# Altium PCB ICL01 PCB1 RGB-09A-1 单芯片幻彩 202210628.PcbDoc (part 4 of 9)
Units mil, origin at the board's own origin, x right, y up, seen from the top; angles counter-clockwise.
Board outline 17436.43 x 6581.89 mil, 2 copper layers (Top Layer, Bottom Layer), stack 65.792 mil thick; 425 components, 516 nets, 1625 pads, 2772 vias.
Unrouted connection lines stored in the file: 1.
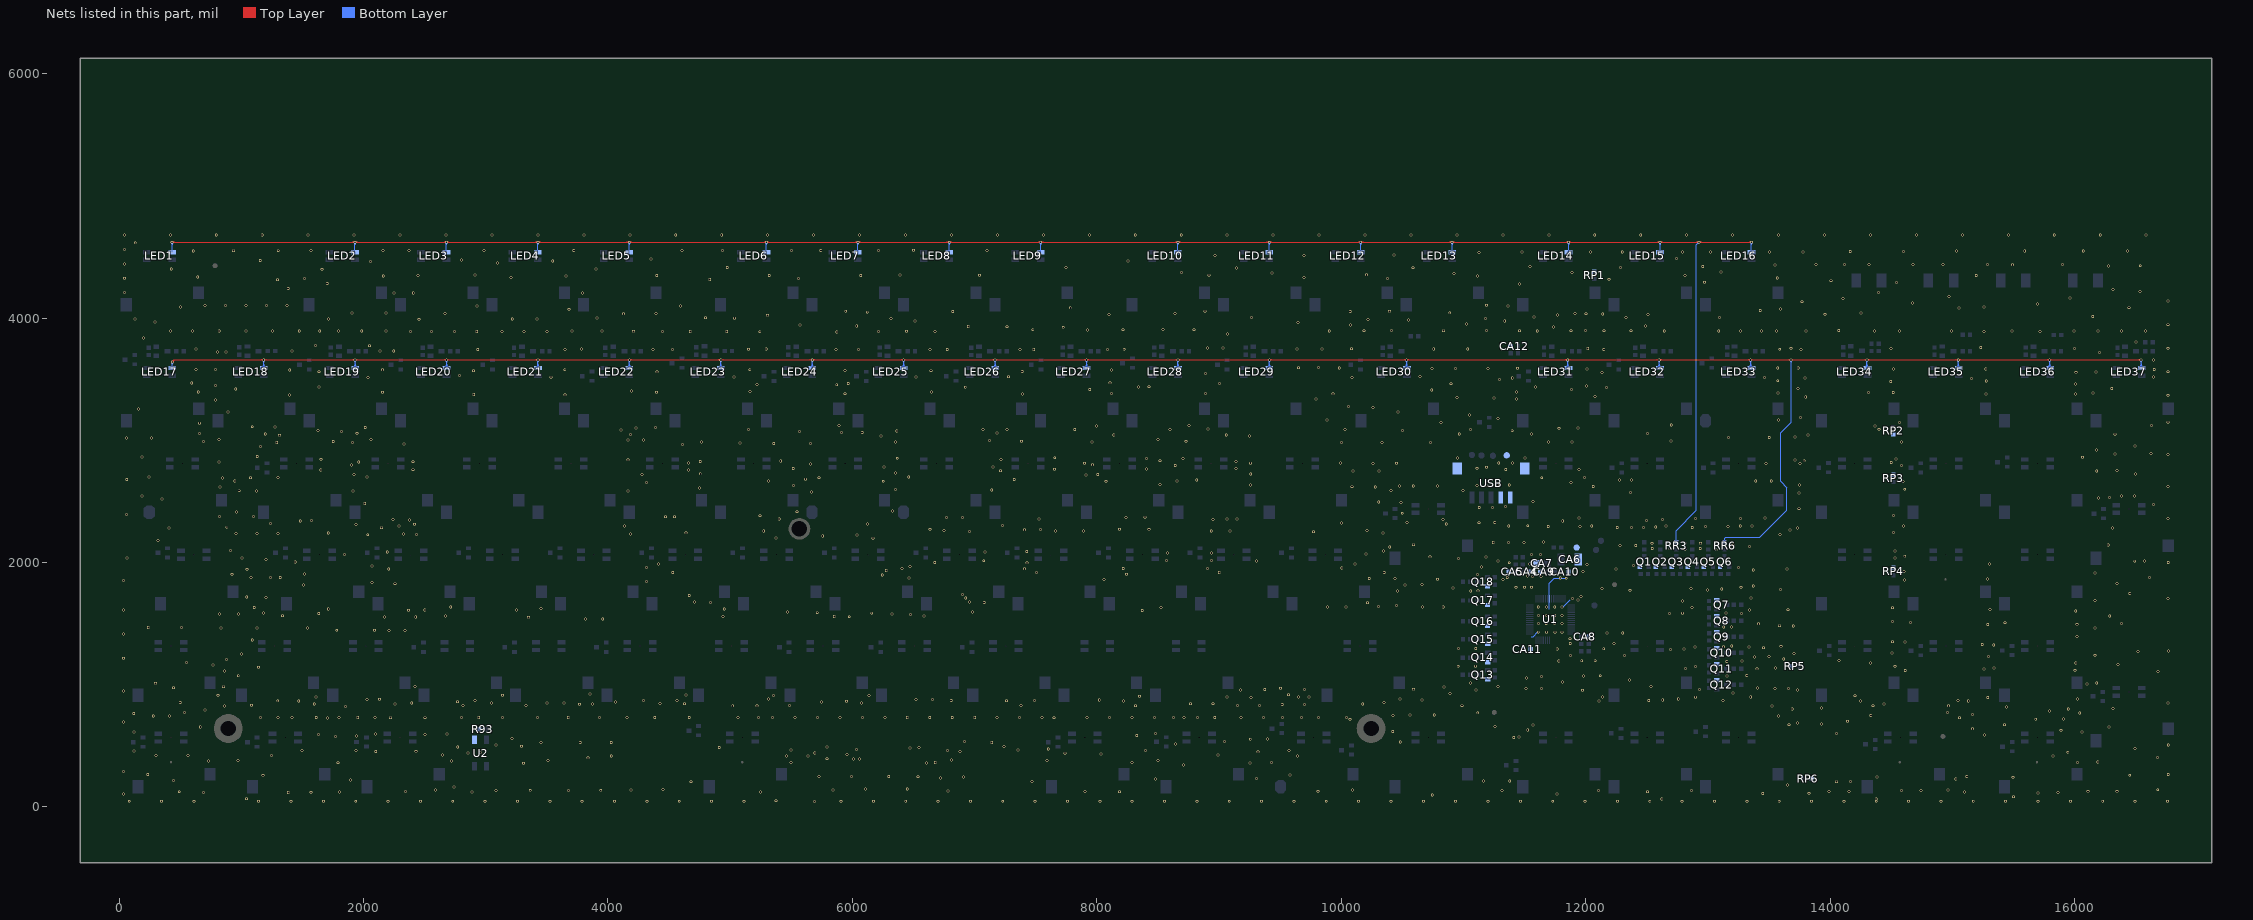
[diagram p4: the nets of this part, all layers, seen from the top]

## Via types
v1: diameter 23.62, hole 15.75, Top Layer to Bottom Layer, tented both sides, 2766 vias
v2: diameter 19.68, hole 11.81, Top Layer to Bottom Layer, tented both sides, 6 vias

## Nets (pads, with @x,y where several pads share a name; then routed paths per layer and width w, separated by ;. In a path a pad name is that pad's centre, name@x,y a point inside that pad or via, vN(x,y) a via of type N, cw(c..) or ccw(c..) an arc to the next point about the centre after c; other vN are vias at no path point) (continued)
GND: CA4.2 CA5.2 CA6.2 CA7.2 CA8.1 CA9.2 CA10.1 CA11.1 CA12.1 pad.3 pad.12 Q1.E Q2.E Q3.E Q4.E Q5.E Q6.E Q7.E Q8.E Q9.E Q10.E Q11.E Q12.E Q13.E Q14.E Q15.E Q16.E Q17.E Q18.E R93.1 RP1.1 RP2.1 RP3.1 RP4.1 RP5.1 RP6.1 U1.56 U2.3 USB.0 USB.1 USB.2 | length 519.8
  Bottom Layer w8: 11555.11,1392.82 11570.25,1392.82 v1@11609.43,1432 ; 11703.42,1617.72 U1.56@11703.42,1703.16 11703.42,1831.8 11744.32,1872.7 11838.9,1872.7 v1(11840.87,1870.73) ; v1@11817.24,1639.8 11873.8,1696.37
  other v1: 5690.72,44.71 83.93,46.43 348.61,46.43 613.3,46.43 1142.68,46.43 1407.36,46.43 1672.05,46.43 1936.74,46.43 2201.42,46.43 2466.11,46.43 2730.8,46.43 2995.49,46.43 3260.17,46.43 3524.86,46.43 3789.55,46.43 4054.23,46.43 4318.92,46.43 4583.61,46.43 4848.3,46.43 5112.98,46.43 5907.04,46.43 6171.73,46.43 6436.42,46.43 6701.11,46.43 6965.79,46.43 7230.48,46.43 7495.17,46.43 7759.85,46.43 8024.54,46.43 8289.23,46.43 8553.91,46.43 8818.6,46.43 9083.29,46.43 9347.98,46.43 9612.66,46.43 9877.35,46.43 10142.04,46.43 10406.72,46.43 10671.41,46.43 10936.1,46.43 11200.79,46.43 11465.47,46.43 11730.16,46.43 11994.85,46.43 12259.53,46.43 12524.22,46.43 12788.91,46.43 13053.6,46.43 13318.28,46.43 13582.97,46.43 13847.66,46.43 14112.34,46.43 14377.03,46.43 14641.72,46.43 14906.41,46.43 15171.09,46.43 15435.78,46.43 15700.47,46.43 15965.15,46.43 16229.84,46.43 16494.53,46.43 16759.22,46.43 5375.47,50.46 14376.62,64.25 12622.41,65.24 1043.39,66.86 15499.68,83.08 10744.58,99.22 11765.88,106.64 35.28,106.96 13448.4,108.4 13826.05,111.82 15701.46,113.59 692.61,118.76 1385.12,119.47 15863.14,118.88 1571.49,120.02 1802.83,121.46 5247.59,121.19 2889.04,122.61 15097.77,122.95 493.1,123.98 8186.31,123.98 12504.37,124.37 2345.16,126.39 7904.29,126 13991.81,126.39 14154.21,126.39 9809.38,128.17 16108.8,127.98 16347.64,127.98 6782.82,131.44 3085.11,134.09 3677.51,134.09 11314.75,134.1 12104.85,134.1 12864.84,134.26 14582.5,133.94 14741.69,135.19 3364.62,136.17 3941.38,136.17 2588.58,137.71 14963.55,137.62 4190.33,139.09 5841.63,139.14 10092.41,139.36 16680,140.49 4450.78,143.16 6448.87,146.1 6108.08,147.93 2741.98,164.33 13649.43,179.9 4681.11,205.83 14053.3,206.49 14165.9,207.19 7468.7,208.51 11378.21,210.92 11162.59,213.61 446.53,215.95 1895.37,219.72 8480.98,227.76 15027.83,228.57 9307.11,231.98 6720.41,236.25 15496.77,242.66 6910,244.49 14383.71,244.11 6535.53,246.84 5992.67,248.02 6297.66,248.02 5726.08,249.28 15117.8,249.73 1177.3,258.91 16450.8,258.94 9582.02,260.3 16766.05,265.27 234.92,266.15 35.48,290.73 8709.33,342.92 3308.74,357.69 9252.21,359.68 6605.98,360.64 1792.41,361.3 5498.7,362.61 6678.61,362.61 8287.04,363.3 9430.27,362.89 16023.49,364.54 16189.64,367.53 2720.16,374.42 731.14,375.53 972.36,378.62 3509.53,379.34 7591.04,378.86 8501.65,379.34 6809.72,385.24 6008.54,392.13 6058.56,393.17 5791.83,394.33 3837.28,401.98 16677.85,402.96 9643.43,415.51 15824.1,415.85 4027.24,417.72 5637.35,417.65 5461.21,417.84 303.82,420.68 565.63,420.68 1246.97,421.29 8990.83,423.63 2647.81,425.87 5955.94,428.88 8034.25,432.3 7741.29,439.61 5692.6,441.35 2855,442.33 2958.64,445.24 15944.24,447.59 9317.98,451.12 6879.74,454.29 2100.37,454.95 2430.66,455.21 122.14,456.18 9572.73,461.35 1497.62,462.54 1939.52,462.25 8398.3,462.65 6779.21,463 5498.7,464.97 7355,464.97 6035.12,468.9 7602.63,473.93 16492.78,478.98 6472.12,483.67 6544.96,485.64 4911.13,487.34 5793.13,489.23 2771.34,491.54 7241.81,493.51 3292.01,496.46 3083.35,505.32 16766.05,506.23 8642.84,514.99 4027.24,525.99 3451.46,526.98 3773.31,526.98 7140,527.07 10482.89,531.47 6916.75,534.47 9046.1,535.99 9255.81,553.72 9396.09,556.16 3215.67,558.5 11410.91,568.79 11455.56,571.74 1770.37,575.95 1942.38,581.91 8327.05,584.38 15261.49,587.02 1632.66,593.88 2505.05,594.18 2100.07,595.84 2682.2,597.44 8481.66,599.52 14051.85,599.81 16060.55,613.38 123.94,614.48 10420.94,615.83 15887.44,627.67 11525.33,630.27 15164.48,639.29 16282.18,653.82 665.04,654.93 11256.31,659.31 11567.19,669.92 13664.05,672.65 15426.05,672.13 13927.83,679.53 13732.68,686.3 35.28,693.82 14142.44,700.8 10070.01,717.16 15681.67,717.64 15909.71,719.93 1707.02,729.18 15058.09,729.53 1158.54,730.22 1299.96,730.22 1415.53,730.22 1613.52,730.22 1952.94,730.22 2094.36,730.22 2222.29,730 2503.44,730 2801.46,730.22 2942.89,730.22 3138.44,730.22 3423.72,730.22 3675.84,730.22 3930.4,730.22 4156.67,730.22 4382.95,730.22 4665.79,730.22 5064.21,730.22 5231.48,730.22 5346.62,730.37 5530.43,730.37 5714.24,730.37 5898.04,730.37 6081.85,730.37 6265.65,730.37 6449.46,730.37 6633.27,730.37 6817.07,730.37 7000.88,730.37 7184.69,730.37 7368.49,730.37 7552.3,730.37 7648.24,729.93 7919.91,730.37 8103.72,730.37 8287.52,730.37 8471.33,730.37 8628.03,730.22 8712.88,730.22 8823.58,730.22 8965,730.22 9363.42,730.22 9814.96,730.57 1798.77,731.34 10042.37,731.29 9179.15,731.95 9520.14,733.18 9674.6,732.78 280.38,744.06 411.74,744.69 13576.57,744.14 10423.74,746.7 14332.36,749.42 10562.32,752.59 10760.62,751.86 15165.76,754.74 120.7,764.75 16041.78,767.41 11116.64,770.21 535.5,773.45 14958.55,772.93 15794.96,783.87 704.71,794.01 13689.44,800.87 15947.98,801.05 16314.94,805.9 13928.86,808.79 15441.78,818.36 1851.99,821.79 862.14,824.44 5021.07,827.5 5219.06,827.5 8315.8,827.71 13523.4,826.97 14968.36,827.49 2814.38,828.73 3330.57,828.66 10988.68,828.24 14351.06,828.16 5485.45,829.1 7380.33,829.59 9149.5,830.79 9331.36,831.38 1083.72,832.25 9698.11,837.39 9516.77,839.32 3768.38,839.97 1597.26,841.73 2257.2,840.87 10175.57,841.36 14439.07,842.01 3875.47,843.02 4626.44,844.44 8766.05,844.33 8950.37,844.16 4427.1,844.79 3046.93,848.83 3639.63,849.43 2394.89,850.14 6073.72,850.54 16764.5,850.98 3502.64,851.78 500.65,855.6 10350.56,856.03 4063.09,857.87 2768.38,860.64 5748.9,859.85 5950.71,864.54 8218.78,865.33 14246.73,865.56 12110.25,865.96 1470.49,867.46 15130.07,867.6 1298.48,868.45 7262.51,868.57 4290.04,869.5 7490.17,869.32 4564.64,870.48 15046.76,870.14 2911.08,871.02 6808.74,871.46 12515.56,871.76 13122.96,871.62 8020.35,873.43 12629.95,873.34 10660.01,875 6521.34,878.35 6657.16,878.35 2029.21,879.34 2132.18,881.19 10479.5,881.75 5314.04,882.74 16023.4,882.92 12757.51,884.41 9261.57,895.39 15289.4,896.85 1610.43,897.88 12136.51,898.16 12897.45,897.87 13349.84,898.26 9650.35,898.86 9736.33,899.59 9063.99,900.64 8350.11,905.76 14202.71,909.44 6135.15,912.43 810.2,913.53 5355.11,913.19 3136.08,914.02 4638.74,914.43 9569.29,917.78 3851.99,922.91 10889.74,927.18 13204.07,933.4 35.28,948.38 9176.91,955.52 11102.62,955.56 11973.28,954.84 13732.27,955.49 9373.73,959.58 9697.91,960.42 10592.28,962.55 12929.54,961.96 11511.31,969.04 13547.5,969.43 13659.48,969.43 11639.05,970.46 9502.41,970.83 13405.04,971.55 446.01,974.99 10840.97,981.26 855.98,983.67 12533.15,984.65 2420.15,986.68 11282.42,986.68 16100.76,1004.94 299.41,1011.59 11058.15,1014.61 16181.27,1014.4 11808.65,1022.26 12357.01,1038.18 11514.86,1056.32 11636.92,1068.39 11981.09,1072.64 13154.85,1072.2 975.96,1073.23 12118.97,1073.39 13317.86,1075.03 16682.65,1107.01 862.25,1113.29 14614.14,1116.04 16001.65,1118.51 15259.89,1128.67 13401.58,1130.27 12815.74,1133.28 13551.41,1136.36 15341.71,1136.51 1141.84,1142.86 12899.29,1149.02 10956.71,1150.79 11099.84,1151.49 14531.18,1150.99 769.67,1161.12 16354.05,1166.5 14328.42,1177.57 16009.63,1179.04 551.71,1182.4 13154.21,1188.39 11779.75,1195.52 13278.76,1194.88 11967.22,1195.83 12077.6,1196.12 14071.39,1196.51 879.38,1207.37 13620.21,1208.79 35.28,1216.73 13379.74,1226.62 13500.57,1229.26 15295.38,1231.59 11877.07,1238.98 12317.73,1239.74 16166.72,1240.73 1003.44,1251.45 13704.35,1254.13 14504.61,1258.28 16519.61,1270.17 16766.6,1276.99 12693.55,1288.5 12804.43,1292.6 11766.78,1293.48 12147.14,1294.05 10958.1,1296.7 11100.53,1296.01 13455.79,1302.33 12894.29,1306.98 13336.15,1309.01 13126.38,1310.17 13598.66,1314.23 13194.58,1316.03 15338.24,1324.44 15244.22,1329.54 12230.88,1337.34 11873.7,1338 14611.71,1350.5 14510.31,1351.56 1090.32,1366.68 11872.17,1375.87 16021.08,1395.74 35.28,1414.72 12175.27,1422.08 12302.91,1424.4 11611.89,1429.53 11678.82,1429.53 11747.72,1429.53 11806.77,1429.53 2340.6,1443.21 1781.31,1445.48 2090.32,1445.46 2209.15,1445.08 1541.98,1463.52 1129.62,1464.19 834.81,1465.49 16166.72,1465.12 239.67,1466.58 511.54,1466.72 13129.62,1473.21 13191.46,1472.8 13697.88,1481.42 13584.47,1482.71 15288.99,1491.25 16020.01,1494.31 13414.18,1498.4 11612.87,1499.42 11806.77,1499.42 11676.85,1500.4 11745.75,1500.4 16384.17,1501.26 15430.07,1506.8 14656.22,1508.09 14508.54,1516.15 3816.87,1537.78 3957.51,1538.99 3350.84,1551.61 2172.91,1552.75 2427.47,1554.83 5974.82,1555.98 4941.18,1557.93 5852.24,1558.06 6586.38,1561.58 16287.51,1561.06 2671.38,1563.64 1339.01,1563.97 11613.86,1566.35 11677.83,1566.35 11806.77,1566.35 11746.73,1567.33 6474.94,1575.27 823.4,1578.02 976.94,1578.84 6323.1,1580.08 13273.21,1581.8 1634.13,1582.96 12685.71,1584.06 6158.56,1585.05 12792.01,1585.05 1181.2,1587.22 13147.32,1588 5712.68,1589.2 6983.81,1593.73 5469.32,1594.97 16009,1602.27 8371.83,1606.24 2369.59,1609.49 2501.83,1609.77 13339.92,1611.72 35.28,1612.72 3252.43,1612 13653.95,1613.19 15308.4,1614.82 1712.31,1620.31 4951.96,1620.71 3451.46,1624.42 14509.51,1629.46 1106.23,1631.06 8526.61,1631.56 12868.06,1632.05 2714.37,1634.56 10664.35,1635.17 10834.05,1635.17 11611.89,1635.24 11677.83,1635.24 11746.73,1635.24 11806.77,1635.24 9888.1,1637.25 10037.88,1637.25 10305.25,1641.44 10452.44,1648.04 10214.37,1670.5 4838.72,1672.85 7078.61,1674.04 4709.41,1676.51 6958.8,1677.5 12792.01,1684.46 16166.72,1689.5 11936.56,1691.94 11893.38,1704.14 16764.65,1705.44 6927.47,1708.19 13353.16,1710.8 1203.9,1714.38 1045.06,1716.84 11962.87,1720.44 4665.68,1728.92 6902.24,1738.59 16451.53,1746.74 11059.4,1765.56 10458.92,1767.61 11118.25,1768.37 12362.87,1773.04 12995.75,1775.01 13592.14,1777.82 13112.87,1783.87 12860.9,1785.83 12133.24,1788.44 10913.67,1792.29 11430.49,1797.47 11498.46,1797.47 11556.54,1797.47 13269.37,1797.65 13370.75,1808.47 10522.9,1815.44 1508.44,1816.32 10661.59,1819.5 2257.18,1826.42 16345.54,1829.21 2068.65,1835.89 4314.5,1845.19 35.28,1853.48 14608.83,1856.61 11324.71,1859.6 8059.42,1862.08 10787.35,1863.01 15287.79,1864.17 10229.23,1868.6 10439.19,1870.45 11791.61,1872.7 6462.91,1874.37 1079.41,1876.39 1237.87,1876.39 11357.9,1877.39 1319.51,1878.71 16614,1878.26 11566.17,1886.46 11634.81,1886.46 11523.3,1889.3 6244.25,1898.89 925.18,1903.48 8243.97,1903.67 11114.31,1902.85 1518.93,1906.94 16166.72,1913.89 9002.09,1916.59 10351.29,1917.69 4530.66,1917.95 7507.96,1918.06 11978.08,1927.28 14605.59,1927.73 6277.62,1935.94 13370.75,1937.41 1045.83,1944.44 2207.11,1945.89 12248.36,1946.7 13646.87,1945.93 7407.45,1948.37 8905.68,1949.21 6405.73,1949.85 8216.25,1949.97 10004.36,1953.61 4314.5,1960.41 13250.22,1960.5 11146.38,1962.73 6472.36,1967.22 2068.65,1969.72 12392.26,1973.99 12009.94,1984.5 4414.95,1987.23 10112,1987.39 11539.19,1988.11 15302.22,1988.08 7429.65,1997.52 11374.39,1997.8 6674.16,2000.76 16765.77,2000.87 1441.53,2005.1 16492.13,2010.42 9307.29,2011.31 11281.65,2013.54 16572.51,2013.03 7074.73,2014.38 8571.54,2014.77 8936.81,2015.09 1201.53,2025.87 10959.63,2031.82 66.02,2037.2 1006.57,2037.8 14529.21,2037.8 11866.43,2043.14 11184.93,2045.38 10725.74,2046.5 14609.85,2050.65 11631.01,2064.43 11555.35,2065.39 1846.38,2066.17 10202.51,2068.6 8578.84,2078.06 8938.37,2077.9 2194.74,2086.06 7083.81,2086.98 7426.61,2090.42 10345.37,2093.43 14529.21,2092.92 913.14,2098.82 13068,2103.75 12812.19,2105.16 12544.13,2113.17 12684.52,2115.05 12937.03,2115.52 10396.96,2126.26 13340.27,2130.35 12280.32,2140.02 12409.12,2140.02 13208.09,2143.69 16274.79,2144.23 10590.28,2145.42 12543.19,2157.45 12681.69,2157.45 12938.44,2156.98 13068.47,2158.39 12813.13,2158.87 11243.88,2162.56 11369.82,2163.06 11495.26,2163.57 11653.57,2166.31 318.34,2178.48 6168.06,2198.59 5376.3,2201.29 5757.33,2216.38 2034.85,2226.72 6037.53,2225.82 2434.42,2227.76 13588.49,2229.4 4186.3,2231.87 2326.33,2233.82 1300.28,2235.58 1129.61,2237.61 957.36,2238.59 1711.78,2240.69 10339.92,2242.1 4639.56,2242.82 14518.78,2244.31 9771.4,2251.29 6957.33,2254.19 5274.67,2257.19 7663.2,2257.27 7891.31,2257.68 9088.19,2257.68 8936.55,2257.77 6749.61,2260.98 10209.04,2263.07 7408.18,2267.47 13671.86,2266.8 7539.96,2268.41 8428.27,2271.55 6634.04,2271.77 8186.79,2272.11 408.56,2280.7 13733.79,2283.1 16309.73,2283.15 2149.16,2284.56 12474.07,2285.62 12257.98,2285.95 12374.4,2286.74 12871.33,2286.52 881.93,2288.61 12573.09,2289.95 12979.21,2293.28 11693.37,2294.5 11954.26,2295 13165.62,2295.16 11370.55,2297.13 12049.42,2297.52 14600.69,2297.28 4136.22,2298.16 13264.64,2298 12655.54,2299.59 13361.27,2299.37 2292.05,2299.79 11525.66,2300.77 7226.9,2302.46 1938.82,2311.24 2419.09,2312.7 6124.02,2313.91 10858.94,2316.35 1238.91,2318.63 10002.87,2324.53 11128.3,2325.4 11256.13,2325.96 10537.53,2328.59 1482.77,2339.07 11811.71,2339.95 1575.47,2341.94 12498.7,2343.9 2375.26,2347.66 2240.46,2351.34 10832.83,2352.14 12627.64,2351.78 8949.7,2352.97 7526.46,2355.47 5401.4,2356.09 9147.7,2356.11 9064.98,2356.94 12897.15,2358.37 13266.39,2358.37 16765.24,2359.47 13465.49,2362.45 11945.58,2364.28 6769.28,2367.76 6902.68,2367.76 8238.96,2369.31 8393.22,2370.48 4470.43,2373.99 4546.26,2373.99 822.64,2374.94 1100.08,2376.39 5245.31,2382.37 14518.78,2383.43 62.87,2391.57 10498.84,2403.05 960.61,2411.58 5547.72,2414.94 6328.6,2420.66 13744.39,2440.04 11236.98,2449.3 11129.22,2450.83 11344.76,2457.52 16646.74,2474.63 2010.21,2483.87 10487.77,2489.99 10306.7,2494.73 11567.21,2498.61 352.86,2518.45 16195.55,2527.75 16285.52,2532.86 16489.6,2542.63 187.96,2543.07 16384.44,2543.09 13745.7,2566.91 12366.38,2573.81 5666.66,2575.97 1123.7,2584.06 4165.72,2585.24 1913.51,2585.85 983.31,2587.22 10406.41,2587.96 10994.45,2589.31 7140.43,2592.72 6353.03,2596.86 14610.1,2599.1 4750.49,2609.73 825.65,2617.73 10278.37,2618.82 10087.27,2620.05 16765.24,2622.2 12061.49,2622.97 10476.86,2624.37 10588.96,2625 10786.77,2627.07 5518.65,2629.97 11111.15,2630.71 11189.2,2631.32 11279.96,2633.13 11374.35,2633.13 9258.82,2633.8 13747.55,2634.8 8515.72,2638.53 4315.63,2653.67 11880.59,2655.91 8075.36,2664.73 14595.28,2663.89 6252.49,2664.84 947.39,2666.24 5315.13,2666.51 13518.1,2666.34 8657.16,2667.6 13391.37,2667.83 12375.79,2673.71 12276.29,2675.3 8817.54,2675.82 63.51,2678.26 7324.61,2678.26 5617.51,2681.43 847.1,2692.24 1074.24,2693.46 5727.46,2693.22 11640.5,2693.36 11990.7,2694.36 1301.53,2695.9 6461.33,2698.57 244.43,2699.17 2028.5,2700.84 7912.46,2716.15 4279.4,2718.44 1923.2,2720.56 8007.37,2719.94 9259.39,2722.56 4755.86,2725.6 16499.19,2725.14 6352.41,2733.07 10308.58,2748.61 7212.56,2750.62 10097.44,2749.9 16181.12,2750.02 16346.27,2751.48 1651.01,2757.02 4660.58,2757.65 2405.23,2759.12 11346.07,2761.51 7655.25,2762.72 11946.56,2762.05 8405.96,2763.42 5516.29,2769.1 9139.25,2768.8 11110.27,2771.03 11187.05,2779.11 7150.32,2780.69 6257.56,2781.59 14583.33,2791.92 8641.65,2793.31 1901.56,2796.67 7965.92,2799.24 5657.24,2805.8 13476.01,2809.46 10260.95,2810.41 13753.88,2810.56 10452.78,2811.7 7898.82,2812.03 9258.82,2812.29 11288.33,2812.99 11401.62,2812.99 9993.16,2814.27 4659.84,2815.49 14499.68,2819.3 818.92,2820.62 1961.36,2821.7 2403.79,2823.89 9140.26,2826.38 4755.29,2827.26 5413.71,2829.23 8515.72,2832.49 13787.63,2831.93 13711.33,2837.13 4164.59,2840.12 7216.6,2842.5 1651.65,2844.72 14538.07,2847.84 8705.58,2850.52 8406.3,2851.08 6367.38,2852.71 10951.78,2854.99 11502.73,2854.99 7655.59,2856.82 16063.24,2861.17 187.96,2862.69 1130.93,2867.44 16765.24,2884.93 16329.94,2888.52 16626.03,2893.14 16180.04,2921.24 1158.79,2950.15 16494.54,2952.1 4609.95,2966.41 2332.74,2969.74 5656.41,2973.59 5356.91,2974.4 5079.41,2978.75 1290.14,2980.71 1909.43,2980.73 10002.16,2981.17 10334.45,2981.17 10730.43,2981.17 6352.49,2985.43 7961.97,2985.38 14582.55,2985.12 4766.22,2986.55 11886.26,2986.57 11695.03,2987.21 691.74,2988.64 1753.1,2991.13 7382.45,2991.7 8729.22,2991.67 12698.57,2993.59 7120.92,2997.3 4164.04,3001.71 4291.54,3000.85 2061.97,3005.61 819.03,3006.05 8499.93,3006.24 62.61,3017.57 267.16,3018.95 13168.69,3022.59 13501.49,3022.59 13713.58,3026.74 9248.76,3035.1 6234.35,3035.79 1311.99,3040.63 9058.96,3041.54 13817.11,3041.76 8138.92,3043.14 4186.02,3048.16 16329.19,3049.59 11555.2,3050.32 1196.5,3052.38 10965.34,3052.58 12506.08,3054.26 659.67,3055.39 1948.2,3057.37 7184.92,3059.31 5912.57,3063.18 6080.55,3063.35 1819.64,3070.52 5567.18,3070.22 6363.52,3076.72 11398.6,3077.57 10502.28,3079.32 1628.25,3079.84 4107.18,3085.28 5151.63,3087.02 7264.19,3087.23 10031.03,3086.88 11058.02,3087.67 8598.94,3088.18 7070.33,3089.56 7819.25,3089.29 14397.97,3089.85 8910.98,3093.01 11783,3098.12 11936.18,3098.74 4228.53,3101.22 2014.37,3102.98 4390.89,3105.69 1275.34,3109.37 1090.12,3110.32 7997.44,3115.14 14368.07,3117.77 8755.08,3119.75 5889.31,3121.66 16629.16,3122.31 12699.61,3124.35 657.04,3139.57 14568.32,3144.21 10816.83,3145.3 16765.24,3147.66 9884.09,3164.84 13578.78,3167.3 11281.76,3177.95 13757.24,3186.08 11048.17,3206.99 10465.24,3229.73 890.68,3230.81 158.17,3257.06 10260.36,3267.65 10060.51,3276.55 789.35,3328.45 9794.14,3336.76 11433.14,3337.35 11250.49,3344.3 10946.49,3348.9 13799.85,3354.58 12075.28,3357.03 16765.16,3368.05 1393.74,3371.03 3648.69,3371.92 2901.94,3375.74 7390.45,3378.63 15274.87,3379.61 16008.01,3379.61 5939.46,3380.48 9932.49,3380.19 8888.11,3381.63 8120.43,3383.42 13571.94,3385.79 16150.3,3387.04 14516.03,3391.3 14314.64,3392.13 648.44,3393.7 2155.17,3392.94 4398.86,3393.01 6647.3,3394.06 11433.63,3394.4 5162.19,3397.97 4193.01,3403.84 10740.19,3412.3 7942.43,3414.99 11884.22,3415.45 955.25,3420.42 13737.77,3422.22 16304.06,3422.95 12169.09,3430.89 6923.92,3433.58 11588.87,3434.33 1634.72,3436.01 8340.75,3436.08 8428.55,3437.88 12006.68,3444.19 789.35,3447.44 5871.84,3454.22 5219.5,3456.65 16008.73,3461.6 10898.76,3462.49 9003.92,3463.17 5966.28,3464.49 595.41,3469.14 8108.8,3470.06 14495.42,3479.32 15277.25,3485.25 13571.18,3487.06 11293.54,3495.87 15155.78,3505.55 13795.03,3509.51 11399.28,3510.76 2037.99,3513.55 10087.94,3512.79 13463.26,3514.6 3534.2,3515.96 16646.65,3516.25 6522.22,3517.6 5030.13,3518.93 7278.68,3519.64 10643.06,3521.09 2785.49,3529.2 8888.04,3546.84 12134.01,3554.38 16011.07,3555.99 16176.09,3559.23 1634.72,3560.61 4400.4,3560.16 16765.16,3560.51 7389.56,3563.28 2900.78,3568.58 6644.28,3569.14 5939.46,3572.16 1396.86,3575.27 8120.66,3574.93 2155.17,3576.48 3647.27,3576.64 5160.87,3576.8 16651.29,3577.46 629.58,3578.5 789.35,3579.03 14518.26,3581.54 15273.34,3583.6 12010.52,3583.85 10741.07,3586.48 10934.61,3587.36 11200.29,3587.36 11443.09,3589.12 9983.44,3591.49 13738.46,3591.26 13571.18,3592.14 9649.56,3593.37 9812.6,3594.62 16644.73,3657.41 16203.12,3719.33 874.84,3720.98 807.33,3722.32 2247.84,3730.67 1415.65,3731.24 2134.45,3731.45 2935.16,3742.12 4367.47,3742.64 4529.56,3742.64 12147.93,3742.35 5866.69,3743.69 6635.17,3743.69 6776.6,3743.69 7370.57,3743.69 7483.7,3743.69 8088.26,3743.72 13762.82,3743.69 3649.48,3743.98 5149.76,3744.44 6051.65,3743.78 13587.25,3744.72 3783.44,3745.32 5295.09,3745.24 8224.03,3744.88 11035.16,3746 11310.14,3746 9637.17,3747.47 9843.97,3747.47 10756.32,3747.29 629.58,3748.2 10084.36,3748.76 12016.22,3750.72 14497.18,3751.23 13678.38,3752.75 15999.36,3751.9 16765.16,3752.96 8907,3753.95 9031.6,3754.7 15232.32,3759.53 2049.19,3773.47 1606.27,3773.87 16501.12,3803.7 200.14,3838.22 9068.76,3870.26 5872.7,3884.41 5242.69,3887.53 3313.62,3888.49 3131.9,3889.48 3501.31,3889.48 6213.38,3888.76 2383.71,3890.42 2556.03,3890.42 2743.9,3890.42 2926.58,3890.42 4674.04,3890.61 4971.92,3890.63 4209.19,3891.45 4446.43,3891.15 6676.62,3891 15260.08,3891.24 15715.72,3891.24 1985.78,3892.58 3707.08,3892.67 3950.9,3892.42 6443.36,3891.96 15995.16,3892.46 16189.77,3892.46 16384.39,3892.46 16579,3892.46 421.22,3893.7 601.48,3893.12 819.76,3893.12 1038.04,3893.12 1256.33,3893.12 1474.61,3893.12 1794.32,3893.71 2184.18,3893.01 14362.45,3892.93 14568.67,3892.93 14993.65,3892.93 15487.9,3892.93 9901.46,3894.55 12642.81,3894.49 13436.73,3894.33 13560.91,3894.72 13802.99,3894.72 1642.27,3894.84 11603.22,3895.11 12369.91,3895.75 13088.5,3895.21 13266.81,3895.46 10185.82,3896.05 10412.02,3896.62 10837.28,3896.34 11457.46,3895.92 11879.84,3896.19 12148.8,3896.06 14070.17,3896.52 11996.87,3896.88 11186.78,3898.91 7924.27,3900.71 7476.2,3903.87 8214.75,3903.86 8793.79,3903.86 8541.98,3905.02 7725.54,3924.17 11736.02,3926.69 7265.14,3928.55 6948.51,3930.15 12490.64,3934.73 6035.45,3935.93 5570.92,3942.53 10074.22,3944.45 16765.16,3945.42 11026.16,3951.6 9647.36,3963.66 295.21,3968.69 6513.67,3977.25 11337.12,3977.29 10548.74,3985.49 10219.62,3988.24 1714.35,3990.57 2454.97,3990.18 3217.3,3990.77 3418.89,3990.77 130.27,3992.42 11179.07,3995.28 6316,3996.42 5034.26,3998.58 3909.96,4001.59 4798.25,4002.4 12328.41,4003.9 9266.68,4005.16 13095.09,4005.29 11577.42,4006.97 16148.55,4011.85 5305.56,4022.46 11770.05,4023.94 8098.71,4029.18 12508.24,4030.31 13957.2,4031 12139.16,4033.17 4128.29,4034.73 2667.46,4035.53 4393.41,4035.7 12002.63,4035.26 8641.07,4036 11913.84,4036.41 2182.89,4040.71 1906.94,4042.37 14251.28,4041.76 10887.39,4042.83 6121.83,4047.77 6821.56,4052.34 5945.46,4055.5 10073.15,4054.81 10393.65,4055.11 8884.3,4055.87 13427.91,4061.84 3680.29,4072.17 13594.98,4074.04 7783.08,4083.72 15054.61,4083.01 16445.41,4084.59 503.25,4089.3 15258.4,4089.64 11364.1,4098.08 4595.18,4099.06 2927.62,4100.03 703.83,4101.45 871.22,4101.45 1038.62,4101.45 1206.01,4101.45 1373.41,4101.45 11188.07,4104.5 15694.77,4113.49 14672.67,4124.25 13770.71,4133.21 16765.16,4137.88 14104.51,4159.59 15961.32,4164.91 14973.11,4175.6 2248.77,4203.3 3792.81,4203.44 2407.82,4204.42 43.75,4208.21 14394.65,4208.15 16535.88,4215.86 16313.04,4231.89 1384.26,4240.37 11457.99,4279.13 1703.29,4283.2 14543.56,4289.22 12972.37,4293.03 14007.81,4305.41 1297.36,4313 4832.77,4315.34 12190.11,4317.31 10377.9,4322.37 5558.23,4323.55 43.75,4325.67 1518.41,4324.91 13567.33,4326.84 9695.55,4330.55 3207.36,4331.11 644.25,4334.83 11114.92,4342.71 3658.68,4343.53 2162.11,4345.21 15195.39,4346.65 2446.84,4348.33 5319.96,4347.99 6068.9,4348.61 12811.13,4348.52 4399.29,4348.82 7039.72,4350.09 8918.98,4350.45 6389.04,4351.04 2913.07,4352.76 10205.96,4353.74 10922.85,4365.23 9434.53,4368.65 8692.83,4371.12 11886.61,4373.67 13108.35,4377.78 1659.33,4399.32 3901.05,4400.75 427.3,4402.33 9141.88,4410.35 10588.2,4411.64 4976.21,4412.59 12283.22,4412.75 7748.76,4414.37 11544.09,4420.87 12957.74,4422.26 16275.92,4426.72 16537.04,4427.78 13549.42,4435.39 15491.48,4435.6 13884.9,4437.05 14117.53,4437.05 15287.93,4437.05 15900.03,4437.05 14316.72,4438.5 14677.29,4438.5 14924.45,4438.5 43.75,4443.14 3095.92,4449.7 2058.57,4463.49 3549,4465.14 8255.28,4466.37 1155.53,4471.24 2800.89,4475.47 4353.25,4482.64 12742.72,4487.61 8965.98,4510.42 9696.68,4512.6 10432.36,4514.52 11128.17,4537.43 11479.19,4538.76 12038.8,4539.61 12298.72,4540.16 12791.6,4540.39 13503.5,4540.55 13022.35,4541.19 13778.66,4541.1 14164.18,4544.97 14600.06,4544.97 15032.08,4546.91 16070.46,4546.91 16433.69,4546.95 15591.67,4548.02 607.61,4549.26 937.83,4550.84 1302.89,4550.84 1569.77,4552.22 3720.83,4551.92 4606.66,4552.59 4936.02,4552.59 6213.8,4552.59 7101.44,4552.59 2160.98,4553.76 2374.11,4553.56 2985.98,4553.75 5501.76,4553.3 5741.77,4553.3 6499.51,4554.58 43.75,4560.61 132.58,4615.51 43.75,4678.07 419.7,4678.07 795.64,4678.07 1171.59,4678.07 1547.54,4678.07 1923.48,4678.07 2299.43,4678.07 2675.38,4678.07 3051.33,4678.07 3427.27,4678.07 3803.22,4678.07 4179.17,4678.07 4555.11,4678.07 4931.06,4678.07 5307.01,4678.07 5682.95,4678.07 6058.9,4678.07 6434.85,4678.07 6810.79,4678.07 7186.74,4678.07 7562.69,4678.07 7938.64,4678.07 8314.58,4678.07 8690.53,4678.07 9066.48,4678.07 9442.42,4678.07 9818.37,4678.07 10194.32,4678.07 10570.26,4678.07 10946.21,4678.07 11322.16,4678.07 11698.1,4678.07 12074.05,4678.07 12450,4678.07 12825.94,4678.07 13201.89,4678.07 13577.84,4678.07 13953.79,4678.07 14329.73,4678.07 14705.68,4678.07 15081.63,4678.07 15457.57,4678.07 15833.52,4678.07 16209.47,4678.07 16585.41,4678.07
GR0: LED1.G LED2.G LED3.G LED4.G LED5.G LED6.G LED7.G LED8.G LED9.G LED10.G LED11.G LED12.G LED13.G LED14.G LED15.G LED16.G RR3.2 | length 18203.8
  Top Layer w7.87: v1(434.67,4620.12) v1(3426.8,4620.12) v1(8663.02,4620.12) v1(10159.08,4620.12) v1(10907.11,4620.12) v1(11859.87,4620.12) v1(12607.9,4620.12) v1(13355.93,4620.12) ; v1@440.24,4614.55 cw(c453.68,4601.11) 453.68,4620.12 cw(c453.68,4639.13) v1@440.24,4625.68 ; v1@1925.16,4614.55 ccw(c1911.72,4601.11) 1911.72,4620.12 ccw(c1911.72,4639.13) v1@1925.16,4625.69 ; v1@1936.3,4614.55 cw(c1949.74,4601.11) 1949.74,4620.12 cw(c1949.74,4639.13) v1@1936.3,4625.69 ; v1@2673.2,4614.55 ccw(c2659.76,4601.11) 2659.75,4620.12 ccw(c2659.76,4639.13) v1@2673.2,4625.69 ; v1@2684.33,4614.55 cw(c2697.77,4601.11) 2697.77,4620.12 cw(c2697.77,4639.13) v1@2684.33,4625.69 ; v1@3421.23,4614.55 ccw(c3407.79,4601.11) 3407.79,4620.12 ccw(c3407.79,4639.13) v1@3421.23,4625.68 ; v1@3432.36,4614.55 cw(c3445.81,4601.11) 3445.81,4620.12 cw(c3445.81,4639.13) v1@3432.36,4625.68 ; v1@4169.26,4614.55 ccw(c4155.82,4601.11) 4155.82,4620.12 ccw(c4155.82,4639.13) v1@4169.26,4625.69 ; v1@4180.4,4614.55 cw(c4193.84,4601.11) 4193.84,4620.12 cw(c4193.84,4639.13) v1@4180.4,4625.69 ; v1@5291.31,4614.55 ccw(c5277.87,4601.11) 5277.86,4620.12 ccw(c5277.87,4639.13) v1@5291.31,4625.69 ; v1@5302.44,4614.55 cw(c5315.88,4601.11) 5315.88,4620.12 cw(c5315.88,4639.13) v1@5302.44,4625.69 ; v1@6039.34,4614.55 ccw(c6025.9,4601.11) 6025.9,4620.12 ccw(c6025.9,4639.13) v1@6039.34,4625.69 ; v1@6050.47,4614.55 cw(c6063.92,4601.11) 6063.92,4620.12 cw(c6063.92,4639.13) v1@6050.47,4625.69 ; v1@6787.37,4614.55 ccw(c6773.93,4601.11) 6773.93,4620.12 ccw(c6773.93,4639.13) v1@6787.37,4625.69 ; v1@6798.51,4614.55 cw(c6811.95,4601.11) 6811.95,4620.12 cw(c6811.95,4639.13) v1@6798.51,4625.69 ; v1@7535.4,4614.55 ccw(c7521.96,4601.11) 7521.96,4620.12 ccw(c7521.96,4639.13) v1@7535.4,4625.69 ; v1@7546.54,4614.55 cw(c7559.98,4601.11) 7559.98,4620.12 cw(c7559.98,4639.13) v1@7546.54,4625.69 ; v1@8657.45,4614.55 ccw(c8644.01,4601.11) 8644.01,4620.12 ccw(c8644.01,4639.13) v1@8657.45,4625.68 ; v1@8668.58,4614.55 cw(c8682.03,4601.11) 8682.03,4620.12 cw(c8682.03,4639.13) v1@8668.58,4625.68 ; v1@9405.48,4614.55 ccw(c9392.04,4601.11) 9392.04,4620.12 ccw(c9392.04,4639.13) v1@9405.48,4625.69 ; v1@9416.62,4614.55 cw(c9430.06,4601.11) 9430.06,4620.12 cw(c9430.06,4639.13) v1@9416.62,4625.69 ; v1@10153.51,4614.55 ccw(c10140.07,4601.11) 10140.07,4620.12 ccw(c10140.07,4639.13) v1@10153.51,4625.68 ; v1@10164.65,4614.55 cw(c10178.09,4601.11) 10178.09,4620.12 cw(c10178.09,4639.13) v1@10164.65,4625.68 ; v1@10901.54,4614.55 ccw(c10888.1,4601.11) 10888.1,4620.12 ccw(c10888.1,4639.13) v1@10901.54,4625.68 ; v1@10912.68,4614.55 cw(c10926.12,4601.11) 10926.12,4620.12 cw(c10926.12,4639.13) v1@10912.68,4625.68 ; v1@11854.3,4614.55 ccw(c11840.86,4601.11) 11840.86,4620.12 ccw(c11840.86,4639.13) v1@11854.3,4625.68 ; v1@11865.43,4614.55 cw(c11878.88,4601.11) 11878.88,4620.12 cw(c11878.88,4639.13) v1@11865.43,4625.68 ; v1@12602.33,4614.55 ccw(c12588.89,4601.11) 12588.89,4620.12 ccw(c12588.89,4639.13) v1@12602.33,4625.68 ; v1@12613.47,4614.55 cw(c12626.91,4601.11) 12626.91,4620.12 cw(c12626.91,4639.13) v1@12613.47,4625.68 ; 12906.36,4620.12 cw(c12906.36,4600.48) v1@12920.24,4614.37 ; 12907.24,4620.12 ccw(c12907.24,4638.5) v1@12920.24,4625.5 ; v1@12931.38,4614.37 cw(c12945.26,4600.48) 12945.26,4620.12 ; v1@12931.38,4625.5 ccw(c12944.38,4638.5) 12944.38,4620.12 ; v1@13350.36,4614.55 ccw(c13336.92,4601.11) 13336.92,4620.12 ccw(c13336.92,4639.13) v1@13350.36,4625.68
  Bottom Layer w7.87: v1@429.1,4614.55 cw(c415.66,4601.11) 434.67,4601.11 cw(c453.68,4601.11) v1@440.24,4614.55 ; LED1.G@434.67,4539.57 v1(434.67,4620.12) ; v1@1925.16,4614.55 cw(c1911.72,4601.11) 1930.73,4601.11 cw(c1949.74,4601.11) v1@1936.3,4614.55 ; LED2.G@1930.73,4539.57 v1(1930.73,4620.12) ; v1@2673.2,4614.55 cw(c2659.76,4601.11) 2678.76,4601.11 cw(c2697.77,4601.11) v1@2684.33,4614.55 ; LED3.G@2678.76,4539.57 v1(2678.76,4620.12) ; v1@3421.23,4614.55 cw(c3407.79,4601.11) 3426.8,4601.11 cw(c3445.81,4601.11) v1@3432.36,4614.55 ; LED4.G@3426.8,4539.57 v1(3426.8,4620.12) ; v1@4169.26,4614.55 cw(c4155.82,4601.11) 4174.83,4601.11 cw(c4193.84,4601.11) v1@4180.4,4614.55 ; LED5.G@4174.83,4539.57 v1(4174.83,4620.12) ; v1@5291.31,4614.55 cw(c5277.87,4601.11) 5296.87,4601.11 cw(c5315.88,4601.11) v1@5302.44,4614.55 ; LED6.G@5296.87,4539.57 v1(5296.87,4620.12) ; v1@6039.34,4614.55 cw(c6025.9,4601.11) 6044.91,4601.11 cw(c6063.92,4601.11) v1@6050.47,4614.55 ; LED7.G@6044.91,4539.57 v1(6044.91,4620.12) ; v1@6787.37,4614.55 cw(c6773.93,4601.11) 6792.94,4601.11 cw(c6811.95,4601.11) v1@6798.51,4614.55 ; LED8.G@6792.94,4539.57 v1(6792.94,4620.12) ; v1@7535.4,4614.55 cw(c7521.96,4601.11) 7540.97,4601.11 cw(c7559.98,4601.11) v1@7546.54,4614.55 ; LED9.G@7540.97,4539.57 v1(7540.97,4620.12) ; v1@8657.45,4614.55 cw(c8644.01,4601.11) 8663.02,4601.11 cw(c8682.03,4601.11) v1@8668.58,4614.55 ; LED10.G@8663.02,4539.57 v1(8663.02,4620.12) ; v1@9405.48,4614.55 cw(c9392.04,4601.11) 9411.05,4601.11 cw(c9430.06,4601.11) v1@9416.62,4614.55 ; LED11.G@9411.05,4539.57 v1(9411.05,4620.12) ; v1@10153.51,4614.55 cw(c10140.07,4601.11) 10159.08,4601.11 cw(c10178.09,4601.11) v1@10164.65,4614.55 ; LED12.G@10159.08,4539.57 v1(10159.08,4620.12) ; v1@10901.54,4614.55 cw(c10888.1,4601.11) 10907.11,4601.11 cw(c10926.12,4601.11) v1@10912.68,4614.55 ; LED13.G@10907.11,4539.57 v1(10907.11,4620.12) ; v1@11854.3,4614.55 cw(c11840.86,4601.11) 11859.87,4601.11 cw(c11878.88,4601.11) v1@11865.43,4614.55 ; LED14.G@11859.87,4539.57 v1(11859.87,4620.12) ; v1@12602.33,4614.55 cw(c12588.89,4601.11) 12607.9,4601.11 cw(c12626.91,4601.11) v1@12613.47,4614.55 ; LED15.G@12607.9,4539.57 v1(12607.9,4620.12) ; RR3.2@12741.63,2165.61 12741.63,2261.22 12906.18,2425.77 12906.18,4600.31 v1(12925.81,4619.93) ; v1@12917.93,4619.93 cw(c12898.93,4619.93) 12912.37,4606.49 cw(c12925.81,4593.05) v1@12925.81,4612.06 ; v1@13350.36,4614.55 cw(c13336.92,4601.11) 13355.93,4601.11 cw(c13374.94,4601.11) v1@13361.5,4614.55 ; LED16.G@13355.93,4539.57 v1(13355.93,4620.12)
GR1: LED17.G LED18.G LED19.G LED20.G LED21.G LED22.G LED23.G LED24.G LED25.G LED26.G LED27.G LED28.G LED29.G LED30.G LED31.G LED32.G LED33.G LED34.G LED35.G LED36.G LED37.G RR6.2 | length 22366.3
  Top Layer w7.87: v1(435.65,3639.65) 452.9,3656.9 v1@16543.92,3656.9 ; v1@435.65,3647.53 ccw(c435.65,3666.54) 449.1,3653.09 ccw(c462.54,3639.65) v1@443.53,3639.65 ; 1164.58,3656.9 cw(c1164.58,3637.55) v1@1178.26,3651.23 ; 1165.06,3656.9 ccw(c1165.06,3675.57) v1@1178.26,3662.37 ; v1@1189.4,3651.23 cw(c1203.08,3637.55) 1203.08,3656.9 ; v1@1189.4,3662.37 ccw(c1202.6,3675.57) 1202.6,3656.9 ; 1912.42,3656.9 ccw(c1912.42,3676.31) v1@1926.14,3662.58 ; 1912.98,3656.9 cw(c1912.98,3638.29) v1@1926.14,3651.45 ; v1@1937.28,3651.45 cw(c1950.44,3638.29) 1950.44,3656.9 ; v1@1937.28,3662.58 ccw(c1951,3676.31) 1951,3656.9 ; 2660.99,3656.9 cw(c2660.99,3637.46) v1@2674.73,3651.2 ; 2661.59,3656.9 ccw(c2661.59,3675.48) v1@2674.73,3662.34 ; v1@2685.87,3651.2 cw(c2699.61,3637.46) 2699.61,3656.9 ; v1@2685.87,3662.34 ccw(c2699.01,3675.48) 2699.01,3656.9 ; 3407.71,3656.9 ccw(c3407.71,3677.21) v1@3422.07,3662.85 ; 3409.55,3656.9 cw(c3409.55,3639.19) v1@3422.07,3651.71 ; v1@3433.21,3651.71 cw(c3445.73,3639.19) 3445.73,3656.9 ; v1@3433.21,3662.85 ccw(c3447.57,3677.21) 3447.57,3656.9 ; 4155.98,3656.9 ccw(c4155.98,3676.62) v1@4169.93,3662.67 ; 4156.99,3656.9 cw(c4156.99,3638.6) v1@4169.93,3651.54 ; v1@4181.07,3651.54 cw(c4194,3638.6) 4194,3656.9 ; v1@4181.07,3662.67 ccw(c4195.01,3676.62) 4195.01,3656.9 ; 4904.06,3656.9 cw(c4904.06,3637.24) v1@4917.96,3651.14 ; 4904.98,3656.9 ccw(c4904.98,3675.25) v1@4917.96,3662.27 ; v1@4929.09,3651.14 cw(c4943,3637.24) 4943,3656.9 ; v1@4929.09,3662.27 ccw(c4942.07,3675.25) 4942.07,3656.9 ; 5652.79,3656.9 ccw(c5652.79,3676) v1@5666.3,3662.49 ; 5652.93,3656.9 cw(c5652.93,3637.98) v1@5666.3,3651.36 ; v1@5677.44,3651.36 cw(c5690.81,3637.98) 5690.81,3656.9 ; v1@5677.44,3662.49 ccw(c5690.95,3676) 5690.95,3656.9 ; 6400.41,3656.9 ccw(c6400.41,3676.3) v1@6414.13,3662.58 ; 6400.97,3656.9 cw(c6400.97,3638.29) v1@6414.13,3651.45 ; v1@6425.27,3651.45 cw(c6438.43,3638.29) 6438.43,3656.9 ; v1@6425.27,3662.58 ccw(c6438.99,3676.3) 6438.99,3656.9 ; 7148.55,3656.9 cw(c7148.55,3637.43) v1@7162.32,3651.19 ; 7149.2,3656.9 ccw(c7149.2,3675.45) v1@7162.32,3662.33 ; v1@7173.45,3651.19 cw(c7187.22,3637.43) 7187.22,3656.9 ; v1@7173.45,3662.33 ccw(c7186.57,3675.45) 7186.57,3656.9 ; 7896.2,3656.9 ccw(c7896.2,3677.15) v1@7910.52,3662.83 ; 7897.96,3656.9 cw(c7897.96,3639.13) v1@7910.52,3651.69 ; v1@7921.66,3651.69 cw(c7934.22,3639.13) 7934.22,3656.9 ; v1@7921.66,3662.83 ccw(c7935.97,3677.15) 7935.97,3656.9 ; 8644.86,3656.9 cw(c8644.86,3637.69) v1@8658.44,3651.27 ; 8645.14,3656.9 ccw(c8645.14,3675.71) v1@8658.44,3662.41 ; v1@8669.58,3651.27 cw(c8683.16,3637.69) 8683.16,3656.9 ; v1@8669.58,3662.41 ccw(c8682.88,3675.71) 8682.88,3656.9 ; 9392.49,3656.9 ccw(c9392.49,3676.06) v1@9406.04,3662.51 ; 9392.71,3656.9 cw(c9392.71,3638.04) v1@9406.04,3651.38 ; v1@9417.18,3651.38 cw(c9430.51,3638.04) 9430.51,3656.9 ; v1@9417.18,3662.51 ccw(c9430.73,3676.06) 9430.73,3656.9 ; 10513.61,3656.9 ccw(c10513.61,3677.97) v1@10528.51,3663.07 ; 10516.53,3656.9 cw(c10516.53,3639.95) v1@10528.51,3651.93 ; v1@10539.65,3651.93 cw(c10551.63,3639.95) 10551.63,3656.9 ; v1@10539.65,3663.07 ccw(c10554.55,3677.97) 10554.55,3656.9 ; 11833.88,3656.9 cw(c11833.88,3637.75) v1@11847.41,3651.29 ; 11834.06,3656.9 ccw(c11834.06,3675.77) v1@11847.41,3662.43 ; v1@11858.55,3651.29 cw(c11872.08,3637.75) 11872.08,3656.9 ; v1@11858.55,3662.43 ccw(c11871.9,3675.77) 11871.9,3656.9 ; 12582.09,3656.9 cw(c12582.09,3637.77) v1@12595.61,3651.3 ; 12582.25,3656.9 ccw(c12582.25,3675.79) v1@12595.61,3662.43 ; v1@12606.75,3651.3 cw(c12620.27,3637.77) 12620.27,3656.9 ; v1@12606.75,3662.43 ccw(c12620.1,3675.79) 12620.1,3656.9 ; v1@13343.44,3651.32 ccw(c13330,3637.88) 13330,3656.89 ccw(c13330,3675.9) v1@13343.44,3662.46 ; v1@13354.58,3651.32 cw(c13368.02,3637.88) 13368.02,3656.89 cw(c13368.02,3675.9) v1@13354.58,3662.46 ; 13660.38,3656.9 cw(c13660.38,3636.87) v1@13674.54,3651.03 ; 13661.82,3656.9 ccw(c13661.82,3674.89) v1@13674.54,3662.17 ; v1@13685.68,3651.03 cw(c13699.84,3636.87) 13699.84,3656.9 ; v1@13685.68,3662.17 ccw(c13698.4,3674.89) 13698.4,3656.9 ; 14280.72,3656.9 ccw(c14280.72,3676.27) v1@14294.41,3662.57 ; 14281.23,3656.9 cw(c14281.23,3638.25) v1@14294.41,3651.44 ; v1@14305.55,3651.44 cw(c14318.73,3638.25) 14318.73,3656.9 ; v1@14305.55,3662.57 ccw(c14319.25,3676.27) 14319.25,3656.9 ; 15028.45,3656.9 ccw(c15028.45,3676.55) v1@15042.34,3662.65 ; 15029.35,3656.9 cw(c15029.35,3638.53) v1@15042.34,3651.52 ; v1@15053.48,3651.52 cw(c15066.47,3638.53) 15066.47,3656.9 ; v1@15053.48,3662.65 ccw(c15067.37,3676.55) 15067.37,3656.9 ; 15776.84,3656.9 ccw(c15776.84,3675.96) v1@15790.32,3662.48 ; 15776.92,3656.9 cw(c15776.92,3637.95) v1@15790.32,3651.35 ; v1@15801.46,3651.35 cw(c15814.86,3637.95) 15814.86,3656.9 ; v1@15801.46,3662.48 ccw(c15814.94,3675.96) 15814.94,3656.9 ; 16524.49,3656.9 ccw(c16524.49,3676.5) v1@16538.35,3662.64 ; 16525.33,3656.9 cw(c16525.33,3638.48) v1@16538.35,3651.5
  Bottom Layer w7.87: v1@430.09,3634.09 cw(c416.64,3620.64) 435.65,3620.64 cw(c454.66,3620.64) v1@441.22,3634.09 ; LED17.G@435.65,3590.75 v1(435.65,3639.65) ; LED18.G@1173.94,3600.49 ccw(c1150.07,3624.36) 1183.83,3624.36 ; v1@1178.26,3651.23 cw(c1164.82,3637.79) 1183.83,3637.79 cw(c1202.84,3637.79) v1@1189.4,3651.23 ; LED18.G@1183.83,3590.89 v1(1183.83,3656.8) ; 1183.83,3623.67 ccw(c1216.61,3623.67) LED18.G@1193.43,3600.49 ; LED19.G@1921.97,3600.49 ccw(c1898.46,3624.01) 1931.71,3624.01 ccw(c1964.99,3624.03) LED19.G@1941.46,3600.49 ; v1@1926.14,3651.45 cw(c1912.7,3638) 1931.71,3638 cw(c1950.72,3638) v1@1937.28,3651.45 ; LED19.G@1931.72,3590.75 v1(1931.71,3657.01) ; LED20.G@2670.01,3600.49 ccw(c2645.15,3625.35) 2680.3,3625.35 ; v1@2674.73,3651.2 cw(c2661.29,3637.76) 2680.3,3637.76 cw(c2699.31,3637.76) v1@2685.87,3651.2 ; LED20.G@2680.3,3591.3 v1(2680.3,3656.77) ; 2680.3,3622.69 ccw(c2711.68,3622.69) LED20.G@2689.49,3600.49 ; LED21.G@3418.04,3600.49 ccw(c3394.85,3623.68) 3427.64,3623.68 ; v1@3422.07,3651.71 cw(c3408.63,3638.27) 3427.64,3638.27 cw(c3446.65,3638.27) v1@3433.21,3651.71 ; LED21.G@3427.64,3590.89 v1(3427.64,3657.28) ; 3427.64,3624.35 ccw(c3461.38,3624.35) LED21.G@3437.52,3600.49 ; LED22.G@4166.07,3600.49 ccw(c4143.3,3623.26) 4175.5,3623.26 ; v1@4169.93,3651.54 cw(c4156.49,3638.1) 4175.5,3638.1 cw(c4194.51,3638.1) v1@4181.07,3651.54 ; LED22.G@4175.5,3591.06 v1(4175.5,3657.11) ; 4175.5,3624.77 ccw(c4209.84,3624.77) LED22.G@4185.56,3600.49 ; LED23.G@4914.1,3600.49 ccw(c4891.34,3623.25) 4923.53,3623.25 ; v1@4917.96,3651.14 cw(c4904.52,3637.7) 4923.53,3637.7 cw(c4942.54,3637.7) v1@4929.09,3651.14 ; LED23.G@4923.53,3591.07 v1(4923.53,3656.71) ; 4923.53,3624.78 ccw(c4957.87,3624.78) LED23.G@4933.59,3600.49 ; LED24.G@5662.13,3600.49 ccw(c5638.62,3624) 5671.87,3624 ccw(c5705.16,3624.03) LED24.G@5681.62,3600.49 ; v1@5666.3,3651.36 cw(c5652.86,3637.92) 5671.87,3637.92 cw(c5690.88,3637.92) v1@5677.44,3651.36 ; LED24.G@5671.87,3590.75 v1(5671.87,3656.92) ; LED25.G@6410.16,3600.49 ccw(c6387.13,3623.52) 6419.7,3623.52 ; v1@6414.13,3651.45 cw(c6400.69,3638) 6419.7,3638 cw(c6438.71,3638) v1@6425.27,3651.45 ; LED25.G@6419.7,3590.95 v1(6419.7,3657.01) ; 6419.7,3624.51 ccw(c6453.67,3624.51) LED25.G@6429.65,3600.49 ; LED26.G@7158.19,3600.49 ccw(c7134.8,3623.89) 7167.89,3623.89 ; v1@7162.32,3651.19 cw(c7148.88,3637.75) 7167.89,3637.75 cw(c7186.9,3637.75) v1@7173.45,3651.19 ; LED26.G@7167.94,3590.75 v1(7167.89,3656.76) ; 7167.89,3624.14 ccw(c7201.33,3624.14) LED26.G@7177.68,3600.49 ; LED27.G@7906.23,3600.49 ccw(c7882.41,3624.31) 7916.09,3624.31 ; v1@7910.52,3651.69 cw(c7897.08,3638.25) 7916.09,3638.25 cw(c7935.1,3638.25) v1@7921.66,3651.69 ; LED27.G@7916.09,3590.87 v1(7916.09,3657.26) ; 7916.09,3623.73 ccw(c7948.95,3623.73) LED27.G@7925.71,3600.49 ; LED28.G@8654.26,3600.49 ccw(c8630.72,3624.04) 8664.01,3624.04 ; v1@8658.44,3651.27 cw(c8645,3637.83) 8664.01,3637.83 cw(c8683.02,3637.83) v1@8669.58,3651.27 ; LED28.G@8664,3590.75 v1(8664.01,3656.84) ; 8664.01,3624 ccw(c8697.25,3624) LED28.G@8673.74,3600.49 ; LED29.G@9402.29,3600.49 ccw(c9379.79,3623) 9411.61,3623 ; v1@9406.04,3651.38 cw(c9392.6,3637.93) 9411.61,3637.93 cw(c9430.62,3637.93) v1@9417.18,3651.38 ; LED29.G@9411.61,3591.17 v1(9411.61,3656.94) ; 9411.61,3625.04 ccw(c9446.32,3625.04) LED29.G@9421.78,3600.49 ; LED30.G@10524.34,3600.49 ccw(c10500.81,3624.02) 10534.08,3624.02 ccw(c10567.34,3624.02) LED30.G@10543.82,3600.49 ; v1@10528.51,3651.93 cw(c10515.07,3638.49) 10534.08,3638.49 cw(c10553.09,3638.49) v1@10539.65,3651.93 ; LED30.G@10534.08,3590.75 v1(10534.08,3657.5) ; LED31.G@11843.23,3600.49 ccw(c11819.7,3624.02) 11852.98,3624.02 ccw(c11886.24,3624.01) LED31.G@11862.72,3600.49 ; v1@11847.41,3651.29 cw(c11833.97,3637.85) 11852.98,3637.85 cw(c11871.99,3637.85) v1@11858.55,3651.29 ; LED31.G@11852.98,3590.75 v1(11852.98,3656.86) ; LED32.G@12591.26,3600.49 ccw(c12567.33,3624.43) 12601.18,3624.43 ; v1@12595.61,3651.3 cw(c12582.17,3637.85) 12601.18,3637.85 cw(c12620.19,3637.85) v1@12606.75,3651.3 ; LED32.G@12601.18,3590.92 v1(12601.18,3656.86) ; 12601.18,3623.61 ccw(c12633.86,3623.61) LED32.G@12610.75,3600.49 ; RR6.2@13135.64,2165.61 13135.64,2198.34 13144.61,2207.3 13425.09,2207.3 13646.75,2428.97 13646.75,2611.21 13595.16,2662.8 13595.16,3063.2 13679.99,3148.03 v1@13679.99,3656.96 ; LED33.G@13339.3,3600.49 ccw(c13315.85,3623.94) 13349.01,3623.94 ; v1@13343.44,3651.32 cw(c13330,3637.88) 13349.01,3637.88 cw(c13368.02,3637.88) v1@13354.58,3651.32 ; LED33.G@13349.01,3590.78 v1(13349.01,3656.89) ; 13349.01,3624.09 ccw(c13382.38,3624.09) LED33.G@13358.78,3600.49 ; v1@13674.54,3651.03 cw(c13661.4,3637.89) 13679.99,3637.89 ; 13679.99,3637.29 cw(c13699.42,3637.29) v1@13685.68,3651.03 ; LED34.G@14290.08,3600.49 ccw(c14266.56,3624.02) 14299.83,3624.02 ccw(c14333.09,3624.02) LED34.G@14309.57,3600.49 ; v1@14294.41,3651.44 cw(c14281.35,3638.37) 14299.83,3638.37 ; LED34.G@14299.83,3590.75 v1@14299.83,3656.85 ; 14299.83,3637.62 cw(c14319.37,3637.62) v1@14305.55,3651.44 ; LED35.G@15038.12,3600.49 ccw(c15014.59,3624.02) 15047.86,3624.02 ccw(c15081.13,3624.02) LED35.G@15057.6,3600.49 ; v1@15042.34,3651.52 cw(c15029.03,3638.2) 15047.86,3638.2 ; LED35.G@15047.86,3590.75 v1(15047.91,3657.08) ; 15047.86,3637.95 cw(c15067.05,3637.95) v1@15053.48,3651.52 ; LED36.G@15786.15,3600.49 ccw(c15762.62,3624.02) 15795.89,3624.02 ccw(c15829.16,3624.02) LED36.G@15805.63,3600.49 ; v1@15790.32,3651.35 cw(c15776.88,3637.9) 15795.89,3637.9 cw(c15814.9,3637.9) v1@15801.46,3651.35 ; LED36.G@15795.89,3590.75 v1(15795.89,3656.91) ; LED37.G@16534.18,3600.49 ccw(c16510.66,3624.02) 16543.92,3624.02 ccw(c16577.19,3624.02) LED37.G@16553.67,3600.49 ; v1@16538.35,3651.5 cw(c16524.91,3638.06) 16543.92,3638.06 cw(c16562.93,3638.06) v1@16549.49,3651.5 ; LED37.G@16543.92,3590.75 v1(16543.92,3657.07)
  other v1: 13680.11,3656.6 14299.98,3657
